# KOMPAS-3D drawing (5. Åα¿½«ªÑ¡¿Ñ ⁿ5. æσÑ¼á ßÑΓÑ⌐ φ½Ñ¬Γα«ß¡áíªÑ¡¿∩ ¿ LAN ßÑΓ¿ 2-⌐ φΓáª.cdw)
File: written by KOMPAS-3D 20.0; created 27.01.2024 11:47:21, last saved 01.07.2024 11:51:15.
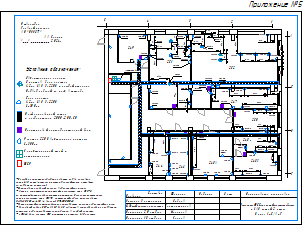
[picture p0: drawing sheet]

Sheet 1: A3, landscape

Document properties: Автор: Пользователь Windows; Организация: НИИЭТ; Полное имя файла: \\Storage\20 Отдел\Мои документы\Крашенинников Е\ТЗ 2й этаж\готово\5. Приложение №5. Схема сетей электроснабжения и LAN сети 2-й этаж.cdw

Title block, sheet 1: scale: 1:1; Количество листов документа: 1; Форматы листов документа: A3

Views: Вид 1, Вид 2, Вид 3, Вид 4
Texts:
  Условные обозначения:
  Блок розеток
  Перфорированный лоток
  с разделителем 2000х200х50
  Утверждаю
  Главный инженер
  АО "НИИЭТ"
  Составил
  Фамилия
  Подпись
  Дата
  Наименование планировки
  Инженер 3 категории
  Дибров
  Приложение №5 Схема сетей электроснабжения
  и LAN сетей 2 этаж.
  В осях 1-5/А-Г.
  Ведущий инженер энергетик
  Крашенинников
  Начальник 20 отдела
  Меренков
  Начальник 18 отдела
  Крюков
  Пластиковый распределительный бокс
  Розетка 220В внутреннего монтажа
  *В каждую комнату необходимо завести по две резервные
  линии LAN сети. (метраж с учетом дальней точки, оставить
  за подвесным потолком).
  *Наименование кабелей указано в однолинейных схемах.
  * Линии к коммутационному шкафу проложить от к. №37Д
  по существующим кабеленесущим системам. Волоконно-оптические
  линии проложить от к. №37Д, оптический кабель использовать
  Netlink ОКСК-4А-1,0 (4 волокна) УТ-00001045.
  *Группы сетей электроснабжения распределить согласно однолинейных схем.
  * Резервный кабель ВВГнг(А) LS 3х2,5, завести в распредкоробку за подвесным
  потолком над распределительным боксом, в каждой комнате.
  * к.№246 блок розеток №5, состоит из четырех LAN розеток.
  Коммутационный шкаф с
  патч-панелями.
  ШСР
  Приложение №5
  БЛОК №1
  БЛОК №2
  БЛОК №3
  БЛОК №4
  БЛОК №5
  БЛОК №8
  БЛОК №10
  БЛОК №6
  БЛОК №7
  БЛОК №9
  БЛОК №13
  БЛОК №12
  БЛОК №11
  Двухсторонняя колонна
  1х2-я LAN, 3х220В с каждой стороны.
  Подвод кабелей по полу в штробе.
  тамбур
  Блок №6
  Блок №7
  Блок №9
  Блок №11
  Блок №14
  розетка 220В, двойная
  яс я
  сфы
  вйв
  cacwq
  Стили документа
  FP_9_ISO 83
  FP_9_ISO 82
  FP_9_ISO 81
  FP_9_ISO 80
  FP_9_ISO 79
  FP_9_ISO 78
  FP_9_ISO 77
  FP_9_ISO 76
  FP_9_ISO 75
  FP_9_ISO 74
  FP_9_ISO 73
  FP_9_ISO 72
  FP_9_ISO 71
  FP_9_ISO 70
  FP_9_ISO 69
  FP_9_ISO 68
  FP_9_ISO 67
  FP_9_ISO 66
  FP_9_ISO 65
  FP_9_ISO 64
  FP_9_ISO 63
  FP_9_ISO 62
  FP_9_ISO 61
  FP_9_ISO 60
  FP_9_ISO 59
  FP_9_ISO 58
  FP_9_ISO 57
  FP_9_ISO 56
  FP_9_ISO 55
  FP_9_ISO 54
  FP_9_ISO 53
  FP_9_ISO 52
  FP_9_ISO 51
  FP_9_ISO 50
  FP_9_ISO 49
  FP_9_ISO 48
  FP_9_ISO 47
  FP_9_ISO 46
  FP_9_ISO 45
  FP_9_ISO 44
  FP_9_ISO 43
  FP_9_ISO 42
  FP_9_ISO 41
  FP_9_ISO 40
  FP_9_ISO 39
  FP_9_ISO 38
  FP_9_ISO 37
  FP_9_ISO 36
  FP_9_ISO 35
  FP_9_ISO 34
  FP_9_ISO 33
  FP_9_ISO 32
  FP_9_ISO 31
  FP_9_ISO 30
  FP_9_ISO 29
  FP_9_ISO 28
  FP_9_ISO 27
  FP_9_ISO 26
  FP_9_ISO 25
  FP_9_ISO 24
  FP_9_ISO 23
  FP_9_ISO 22
  FP_9_ISO 21
  FP_9_ISO 20
  FP_9_ISO 19
  FP_9_ISO 18
  FP_9_ISO 17
  FP_9_ISO 16
  FP_9_ISO 15
  FP_9_ISO 14
  FP_9_ISO 13
  FP_9_ISO 12
  FP_10_ISO 83
  FP_10_ISO 82
  FP_10_ISO 81
  FP_10_ISO 80
  FP_10_ISO 79
  FP_10_ISO 78
  FP_10_ISO 77
  FP_10_ISO 76
  FP_10_ISO 75
  FP_10_ISO 74
  FP_10_ISO 73
  FP_10_ISO 72
  FP_10_ISO 71
  FP_10_ISO 70
  FP_10_ISO 69
  FP_10_ISO 68
  FP_10_ISO 67
  FP_10_ISO 66
  FP_10_ISO 65
  FP_10_ISO 64
  FP_10_ISO 63
  FP_10_ISO 62
  FP_10_ISO 61
  FP_10_ISO 60
  FP_10_ISO 59
  FP_10_ISO 58
  FP_10_ISO 57
  FP_10_ISO 56
  FP_10_ISO 55
  FP_10_ISO 54
  FP_10_ISO 53
  FP_10_ISO 52
  FP_10_ISO 51
  FP_10_ISO 50
  FP_10_ISO 49
  FP_10_ISO 48
  FP_10_ISO 47
  FP_10_ISO 46
  FP_10_ISO 45
  FP_10_ISO 44
  FP_10_ISO 43
  FP_10_ISO 42
  FP_10_ISO 41
  FP_10_ISO 40
  FP_10_ISO 39
  FP_10_ISO 38
  FP_10_ISO 37
  FP_10_ISO 36
  FP_10_ISO 35
  FP_10_ISO 34
  FP_10_ISO 33
  FP_10_ISO 32
  FP_10_ISO 31
  FP_10_ISO 30
  FP_10_ISO 29
  FP_10_ISO 28
  FP_10_ISO 27
  FP_10_ISO 26
  FP_10_ISO 25
  FP_10_ISO 24
  FP_10_ISO 23
  FP_10_ISO 22
  FP_10_ISO 21
  FP_10_ISO 20
  FP_10_ISO 19
  FP_10_ISO 18
  FP_10_ISO 17
  FP_10_ISO 16
  FP_10_ISO 15
  FP_10_ISO 14
  FP_10_ISO 13
  FP_10_ISO 12
  FP_11_ISO 83
  FP_11_ISO 82
  FP_11_ISO 81
  FP_11_ISO 80
  FP_11_ISO 79
  FP_11_ISO 78
  FP_11_ISO 77
  FP_11_ISO 76
  FP_11_ISO 75
  FP_11_ISO 74
  FP_11_ISO 73
  FP_11_ISO 72
  FP_11_ISO 71
  FP_11_ISO 70
  FP_11_ISO 69
  FP_11_ISO 68
  FP_11_ISO 67
  FP_11_ISO 66
  FP_11_ISO 65
  FP_11_ISO 64
  FP_11_ISO 63
  FP_11_ISO 62
  FP_11_ISO 61
  FP_11_ISO 60
  FP_11_ISO 59
  FP_11_ISO 58
  FP_11_ISO 57
  FP_11_ISO 56
  FP_11_ISO 55
  FP_11_ISO 54
  FP_11_ISO 53
  FP_11_ISO 52
  FP_11_ISO 51
  FP_11_ISO 50
  FP_11_ISO 49
  FP_11_ISO 48
  FP_11_ISO 47
  FP_11_ISO 46
  FP_11_ISO 45
  FP_11_ISO 44
  FP_11_ISO 43
  FP_11_ISO 42
  FP_11_ISO 41
  FP_11_ISO 40
  FP_11_ISO 39
  FP_11_ISO 38
  FP_11_ISO 37
  FP_11_ISO 36
  FP_11_ISO 35
  FP_11_ISO 34
  FP_11_ISO 33
  FP_11_ISO 32
  FP_11_ISO 31
  FP_11_ISO 30
  FP_11_ISO 29
  FP_11_ISO 28
  FP_11_ISO 27
  FP_11_ISO 26
  FP_11_ISO 25
  FP_11_ISO 24
  FP_11_ISO 23
  FP_11_ISO 22
  FP_11_ISO 21
  FP_11_ISO 20
  FP_11_ISO 19
  FP_11_ISO 18
  FP_11_ISO 17
  FP_11_ISO 16
  FP_11_ISO 15
  FP_11_ISO 14
  FP_11_ISO 13
  FP_11_ISO 12
  Без основной надписи.
Dimensions and other numbers on the sheet: 1х2-я LAN, 3х220В; 1850; 1000; 3450; 2940; 200; 850; 1600; 800; 2900; 3370; 1500; 950; 989; 801; 405; 500; 525; 350; 3000; 2700; 1700; 600; 1300; 2050; 1400; 4360; 2500; 249; 251; 252; 247; 250; 248а; 248б; 248в; 246; 244; 4200; 8 постов.  блок розеток; 1; 2; 3; 4; 5; 1:1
